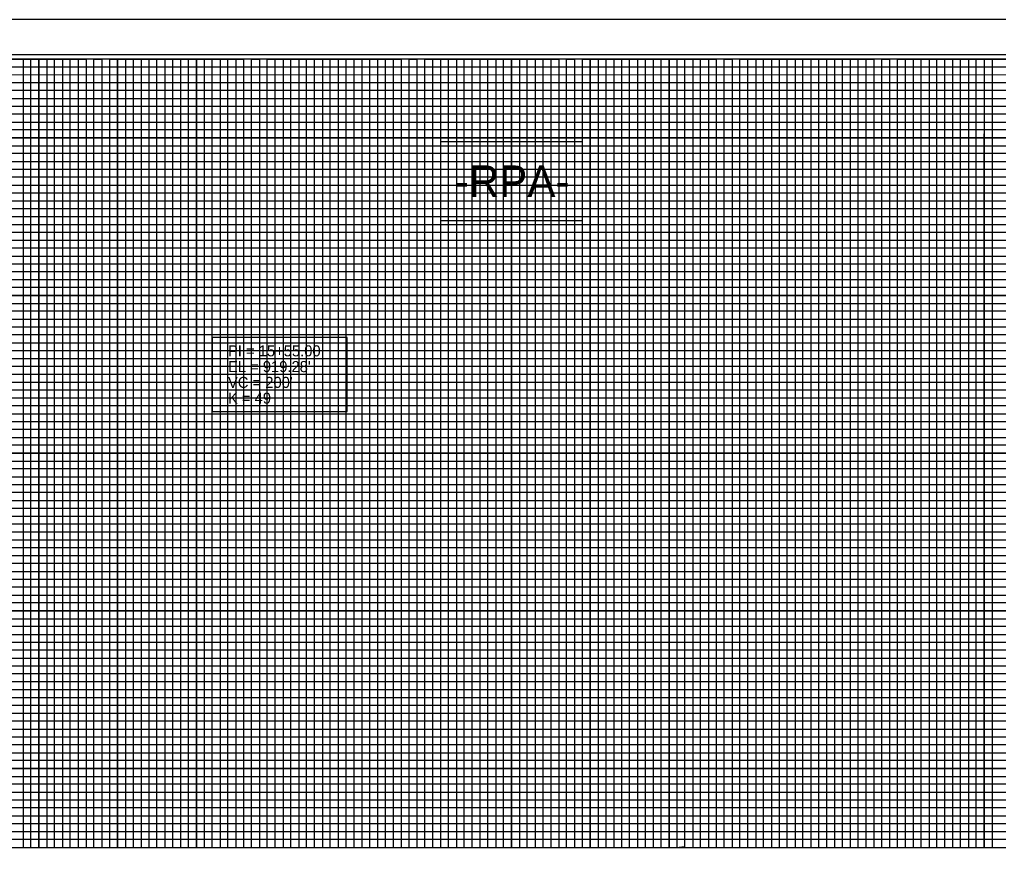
# Model space of a CAD drawing. Extents: x 1648862 to 1650715, y 820691 to 821791.
# Drawn here: x 1649467 to 1650088, y 821252 to 821791 of the extents above; entities that cross this region are included whole.
import ezdxf

# ---------------------------------------------------------------- set-up
doc = ezdxf.new("R2010")
doc.units = 0
for name, color, linetype in [('Exist Vertical Profile Horizontal Axis Label Major', 7, 'Continuous'), ('Prop Grid Mask', 7, 'Continuous'), ('Prop Vertical Profile Curve Label', 7, 'Continuous'), ('Prop VPI Label', 7, 'Continuous'), ('Sheet Cutting Line CELL', 7, 'Continuous'), ('Sheet DOT Grid CELL', 7, 'Continuous'), ('Sheet Layout Profile Border Port 1', 7, 'Continuous'), ('Sheet Plot Border Inside CELL', 7, 'Continuous'), ('Sheet Plot Border Outside CELL', 7, 'Continuous'), ('Sheet Profile CELL', 7, 'Continuous'), ('Sheet Profile Grid Major CELL', 7, 'Continuous'), ('Sheet Profile Grid Middle CELL', 7, 'Continuous'), ('Sheet Profile Grid Minor CELL', 7, 'Continuous')]:
    doc.layers.add(name, color=color, linetype=linetype)

msp = doc.modelspace()

# ---------------------------------------------------------------- linework, layer by layer
at = {"layer": 'Prop Grid Mask'}
for points in [[(1649734.28, 821713.52), (1649734.28, 821663.52), (1649824.28, 821663.52), (1649824.28, 821713.52)], [(1649589.28, 821589.43), (1649589.28, 821542.43), (1649674.97, 821542.43), (1649674.97, 821589.43)]]:
    msp.add_lwpolyline(points, close=True, dxfattribs=at)
at = {"layer": 'Sheet Cutting Line CELL'}
msp.add_line((1650546.28, 821791.02), (1648862.28, 821791.02), dxfattribs=at)
at = {"layer": 'Sheet DOT Grid CELL'}
for p, q in [((1649479.28, 821266.02), (1649479.28, 821766.02)), ((1649529.28, 821266.02), (1649529.28, 821766.02)), ((1649579.28, 821266.02), (1649579.28, 821766.02)), ((1649629.28, 821266.02), (1649629.28, 821766.02)), ((1649679.28, 821266.02), (1649679.28, 821766.02)), ((1649729.28, 821266.02), (1649729.28, 821766.02)), ((1649779.28, 821266.02), (1649779.28, 821766.02)), ((1649829.28, 821266.02), (1649829.28, 821766.02)), ((1649879.28, 821266.02), (1649879.28, 821766.02)), ((1649929.28, 821266.02), (1649929.28, 821766.02)), ((1649979.28, 821266.02), (1649979.28, 821766.02)), ((1650029.28, 821266.02), (1650029.28, 821766.02)), ((1650079.28, 821266.02), (1650079.28, 821718.48)), ((1650329.23, 821716.02), (1649029.28, 821716.02)), ((1650329.23, 821666.02), (1649029.28, 821666.02)), ((1650329.28, 821616.02), (1649029.28, 821616.02)), ((1650529.28, 821566.02), (1649029.28, 821566.02)), ((1650529.28, 821516.02), (1649029.28, 821516.02)), ((1650529.28, 821466.02), (1649029.28, 821466.02)), ((1650529.28, 821416.02), (1649029.28, 821416.02)), ((1650529.28, 821366.02), (1649029.28, 821366.02)), ((1650529.28, 821316.02), (1649029.28, 821316.02))]:
    msp.add_line(p, q, dxfattribs=at)
at = {"layer": 'Sheet Layout Profile Border Port 1'}
msp.add_lwpolyline([(1649079.28, 821604.97), (1649079.28, 821266.02), (1650479.28, 821266.02), (1650479.28, 821604.97)], dxfattribs=at)
at = {"layer": 'Sheet Plot Border Inside CELL'}
msp.add_lwpolyline([(1648875.28, 820713.47), (1650541.78, 820713.47), (1650541.78, 821768.57), (1648875.28, 821768.57)], close=True, dxfattribs=at)
at = {"layer": 'Sheet Plot Border Outside CELL'}
msp.add_lwpolyline([(1648862.28, 820691.02), (1650546.28, 820691.02), (1650546.28, 821791.02), (1648862.28, 821791.02)], close=True, dxfattribs=at)
at = {"layer": 'Sheet Profile CELL'}
msp.add_line((1649029.28, 821266.02), (1650529.28, 821266.02), dxfattribs=at)
msp.add_lwpolyline([(1650529.28, 821766.02), (1649029.28, 821766.02), (1649029.28, 820716.02), (1650529.28, 820716.02)], close=True, dxfattribs=at)
at = {"layer": 'Sheet Profile Grid Major CELL'}
for points in [[(1649429.23, 821766.02), (1649479.23, 821766.02), (1649479.23, 821266.02), (1649529.23, 821266.02), (1649529.23, 821766.02), (1649579.23, 821766.02), (1649579.23, 821266.02), (1649629.23, 821266.02), (1649629.23, 821766.02), (1649679.23, 821766.02), (1649679.23, 821266.02), (1649729.23, 821266.02), (1649729.23, 821766.02), (1649779.23, 821766.02), (1649779.23, 821266.02), (1649829.23, 821266.02), (1649829.23, 821766.02), (1649879.23, 821766.02), (1649879.23, 821266.02), (1649929.23, 821266.02), (1649929.23, 821766.02), (1649979.23, 821766.02), (1649979.23, 821266.02), (1650029.23, 821266.02), (1650029.23, 821766.02), (1650079.23, 821766.02), (1650079.23, 821266.02), (1650129.23, 821266.02)], [(1649029.23, 821716.02), (1650329.23, 821716.02)], [(1650329.23, 821666.02), (1649029.23, 821666.02), (1649029.23, 821616.02), (1650329.23, 821616.02)], [(1650529.23, 821566.02), (1649029.23, 821566.02), (1649029.23, 821516.02), (1650529.23, 821516.02)], [(1650529.23, 821466.02), (1649029.23, 821466.02), (1649029.23, 821416.02), (1650529.23, 821416.02)], [(1650529.23, 821366.02), (1649029.23, 821366.02), (1649029.23, 821366.02), (1649029.23, 821316.02), (1650529.23, 821316.02)]]:
    msp.add_lwpolyline(points, dxfattribs=at)
at = {"layer": 'Sheet Profile Grid Middle CELL'}
msp.add_line((1649029.23, 821741.02), (1650179.23, 821741.02), dxfattribs=at)
for points in [[(1649454.23, 821766.02), (1649504.23, 821766.02), (1649504.23, 821266.02), (1649554.23, 821266.02), (1649554.23, 821766.02), (1649604.23, 821766.02), (1649604.23, 821266.02), (1649654.23, 821266.02), (1649654.23, 821266.02), (1649654.23, 821766.02), (1649704.23, 821766.02), (1649704.23, 821266.02), (1649754.23, 821266.02), (1649754.23, 821766.02), (1649804.23, 821766.02), (1649804.23, 821266.02), (1649854.23, 821266.02), (1649854.23, 821766.02), (1649904.23, 821766.02), (1649904.23, 821266.02), (1649954.23, 821266.02), (1649954.23, 821766.02), (1650004.23, 821766.02), (1650004.23, 821266.02), (1650054.23, 821266.02), (1650054.23, 821766.02), (1650104.23, 821766.02)], [(1650329.23, 821691.02), (1649029.23, 821691.02), (1649029.23, 821641.02), (1650329.23, 821641.02)], [(1650529.23, 821591.02), (1649029.23, 821591.02), (1649029.23, 821541.02), (1650354.23, 821541.02)], [(1650529.23, 821491.02), (1649029.23, 821491.02), (1649029.23, 821441.02), (1650529.23, 821441.02)], [(1650529.23, 821391.02), (1649029.23, 821391.02), (1649029.23, 821341.02), (1650529.23, 821341.02)], [(1650529.23, 821291.02), (1649029.23, 821291.02)]]:
    msp.add_lwpolyline(points, dxfattribs=at)
at = {"layer": 'Sheet Profile Grid Minor CELL'}
for p, q in [((1649079.23, 821761.02), (1650179.23, 821761.02)), ((1650179.23, 821755.98), (1649079.23, 821755.67)), ((1649079.28, 821761.02), (1650037.42, 821761.02)), ((1649079.23, 821751.02), (1650179.23, 821751.02)), ((1650329.18, 821631.02), (1649079.23, 821631.02)), ((1650329.23, 821626.02), (1649079.23, 821626.02)), ((1650329.23, 821621.02), (1649079.23, 821621.02)), ((1649079.23, 821611.02), (1650329.23, 821611.02)), ((1650329.23, 821606.02), (1649079.23, 821606.02)), ((1649079.23, 821601.02), (1650479.23, 821601.02)), ((1650479.23, 821581.02), (1649079.23, 821581.02)), ((1649079.23, 821576.02), (1650479.23, 821576.02)), ((1650479.23, 821556.02), (1649079.23, 821556.02)), ((1649079.23, 821551.02), (1650479.23, 821551.02)), ((1650479.23, 821531.02), (1649079.23, 821531.02)), ((1649079.23, 821526.02), (1650479.23, 821526.02)), ((1650479.23, 821521.02), (1649079.23, 821521.02)), ((1649079.23, 821511.02), (1650479.23, 821511.02)), ((1650479.23, 821506.02), (1649079.23, 821506.02)), ((1649079.23, 821501.02), (1650479.23, 821501.02)), ((1650479.23, 821496.02), (1649079.23, 821496.02)), ((1649079.23, 821486.02), (1650479.23, 821486.02)), ((1650479.23, 821481.02), (1649079.23, 821481.02)), ((1649079.23, 821476.02), (1650479.23, 821476.02)), ((1650479.23, 821471.02), (1649079.23, 821471.02)), ((1649079.23, 821461.02), (1650479.23, 821461.02)), ((1650479.23, 821456.02), (1649079.23, 821456.02)), ((1649079.23, 821451.02), (1650479.23, 821451.02)), ((1650479.23, 821446.02), (1649079.23, 821446.02)), ((1649079.23, 821436.02), (1650479.23, 821436.02)), ((1650479.23, 821431.02), (1649079.23, 821431.02)), ((1649079.23, 821426.02), (1650479.23, 821426.02)), ((1650479.23, 821421.02), (1649079.23, 821421.02)), ((1649079.23, 821411.02), (1650479.23, 821411.02)), ((1650479.23, 821406.02), (1649079.23, 821406.02)), ((1649079.23, 821401.02), (1650479.23, 821401.02)), ((1650479.23, 821396.02), (1649079.23, 821396.02)), ((1649079.23, 821386.02), (1650479.23, 821386.02)), ((1650479.23, 821381.02), (1649079.23, 821381.02)), ((1650479.23, 821376.02), (1649079.23, 821376.02)), ((1650479.23, 821371.02), (1649079.23, 821371.02)), ((1649079.23, 821361.02), (1650479.23, 821361.02)), ((1650479.23, 821356.02), (1649079.23, 821356.02)), ((1649079.23, 821351.02), (1650479.23, 821351.02)), ((1650479.23, 821346.02), (1649079.23, 821346.02)), ((1649079.23, 821336.02), (1650479.23, 821336.02)), ((1650479.23, 821331.02), (1649079.23, 821331.02)), ((1649079.23, 821326.02), (1650479.23, 821326.02)), ((1650479.23, 821321.02), (1649079.23, 821321.02)), ((1649079.23, 821311.02), (1650479.23, 821311.02)), ((1650479.23, 821306.02), (1649079.23, 821306.02)), ((1649079.23, 821301.02), (1650479.23, 821301.02)), ((1650479.23, 821296.02), (1649079.23, 821296.02)), ((1649079.23, 821286.02), (1650479.23, 821286.02)), ((1650479.23, 821281.02), (1649079.23, 821281.02)), ((1649079.23, 821276.02), (1650479.23, 821276.02))]:
    msp.add_line(p, q, dxfattribs=at)
for points in [[(1649464.23, 821766.02), (1649469.23, 821766.02), (1649469.23, 821266.02), (1649474.23, 821266.02), (1649474.23, 821766.02), (1649484.23, 821766.02), (1649484.23, 821266.02), (1649489.23, 821266.02), (1649489.23, 821766.02), (1649494.23, 821766.02), (1649494.23, 821266.02), (1649499.23, 821266.02), (1649499.23, 821766.02), (1649509.23, 821766.02), (1649509.23, 821266.02), (1649514.23, 821266.02), (1649514.23, 821766.02), (1649519.23, 821766.02), (1649519.23, 821266.02), (1649524.23, 821266.02), (1649524.23, 821766.02), (1649534.23, 821766.02), (1649534.23, 821266.02), (1649539.23, 821266.02), (1649539.23, 821766.02), (1649544.23, 821766.02), (1649544.23, 821266.02), (1649549.23, 821266.02), (1649549.23, 821766.02), (1649559.23, 821766.02), (1649559.23, 821266.02), (1649564.23, 821266.02), (1649564.23, 821766.02), (1649569.23, 821766.02), (1649569.23, 821266.02), (1649574.23, 821266.02), (1649574.23, 821766.02), (1649584.23, 821766.02), (1649584.23, 821266.02), (1649589.23, 821266.02), (1649589.23, 821766.02), (1649594.23, 821766.02), (1649594.23, 821266.02), (1649599.23, 821266.02), (1649599.23, 821766.02), (1649609.23, 821766.02)], [(1649609.23, 821766.02), (1649609.23, 821266.02), (1649614.23, 821266.02), (1649614.23, 821766.02), (1649619.23, 821766.02), (1649619.23, 821266.02), (1649624.23, 821266.02), (1649624.23, 821766.02), (1649634.23, 821766.02), (1649634.23, 821266.02), (1649639.23, 821266.02), (1649639.23, 821766.02), (1649644.23, 821766.02), (1649644.23, 821266.02), (1649649.23, 821266.02), (1649649.23, 821766.02), (1649659.23, 821766.02), (1649659.23, 821266.02), (1649664.23, 821266.02), (1649664.23, 821766.02), (1649669.23, 821766.02), (1649669.23, 821266.02), (1649674.23, 821266.02), (1649674.23, 821766.02), (1649684.23, 821766.02), (1649684.23, 821266.02), (1649689.23, 821266.02), (1649689.23, 821766.02), (1649694.23, 821766.02), (1649694.23, 821266.02), (1649699.23, 821266.02), (1649699.23, 821766.02), (1649709.23, 821766.02), (1649709.23, 821266.02), (1649714.23, 821266.02), (1649714.23, 821766.02), (1649719.23, 821766.02), (1649719.23, 821266.02), (1649724.23, 821266.02), (1649724.23, 821766.02), (1649734.23, 821766.02), (1649734.23, 821266.02), (1649734.23, 821266.02), (1649739.23, 821266.02), (1649739.23, 821766.02), (1649744.23, 821766.02), (1649744.23, 821266.02), (1649749.23, 821266.02), (1649749.23, 821766.02), (1649759.23, 821766.02), (1649759.23, 821266.02), (1649764.23, 821266.02), (1649764.23, 821766.02), (1649769.23, 821766.02), (1649769.23, 821266.02), (1649774.23, 821266.02), (1649774.23, 821766.02), (1649784.23, 821766.02), (1649784.23, 821266.02), (1649789.23, 821266.02), (1649789.23, 821766.02), (1649794.23, 821766.02), (1649794.23, 821266.02), (1649799.23, 821266.02), (1649799.23, 821766.02), (1649809.23, 821766.02), (1649809.23, 821266.02), (1649814.23, 821266.02), (1649814.23, 821766.02), (1649819.23, 821766.02), (1649819.23, 821266.02), (1649824.23, 821266.02), (1649824.23, 821766.02), (1649834.23, 821766.02), (1649834.23, 821266.02), (1649839.23, 821266.02), (1649839.23, 821766.02), (1649844.23, 821766.02), (1649844.23, 821266.02), (1649849.23, 821266.02), (1649849.23, 821766.02), (1649859.23, 821766.02), (1649859.23, 821266.02), (1649864.23, 821266.02), (1649864.23, 821766.02), (1649869.23, 821766.02), (1649869.23, 821266.02), (1649874.23, 821266.02), (1649874.23, 821766.02), (1649884.23, 821766.02), (1649884.23, 821266.02), (1649888.93, 821266.57), (1649889.23, 821266.02), (1649889.23, 821766.02), (1649894.23, 821766.02), (1649894.23, 821266.02), (1649899.23, 821266.02), (1649899.23, 821766.02), (1649909.23, 821766.02), (1649909.23, 821266.02), (1649914.23, 821266.02)], [(1649914.23, 821266.02), (1649914.23, 821766.02), (1649919.23, 821766.02), (1649919.23, 821266.02), (1649924.23, 821266.02), (1649924.23, 821766.02), (1649934.23, 821766.02), (1649934.23, 821266.02), (1649939.23, 821266.02), (1649939.23, 821766.02), (1649944.23, 821766.02), (1649944.23, 821266.02), (1649949.23, 821266.02), (1649949.23, 821766.02), (1649959.23, 821766.02), (1649959.23, 821266.02), (1649964.23, 821266.02), (1649964.23, 821766.02), (1649969.23, 821766.02), (1649969.23, 821266.02), (1649974.23, 821266.02), (1649974.23, 821766.02), (1649984.23, 821766.02), (1649984.23, 821266.02), (1649989.23, 821266.02), (1649989.23, 821766.02), (1649994.23, 821766.02), (1649994.23, 821266.02), (1649999.23, 821266.02), (1649999.23, 821766.02), (1650009.23, 821766.02), (1650009.23, 821266.02), (1650014.23, 821266.02), (1650014.23, 821766.02), (1650019.23, 821766.02), (1650019.23, 821266.02), (1650024.23, 821266.02), (1650024.23, 821766.02), (1650034.23, 821766.02), (1650034.23, 821266.02), (1650039.23, 821266.02), (1650039.23, 821766.02), (1650044.23, 821766.02), (1650044.23, 821266.02), (1650049.23, 821266.02), (1650049.23, 821766.02), (1650059.23, 821766.02), (1650059.23, 821266.02), (1650064.23, 821266.02), (1650064.23, 821766.02), (1650069.23, 821766.02), (1650069.23, 821266.02), (1650074.23, 821266.02), (1650074.23, 821766.02), (1650084.23, 821766.02), (1650084.23, 821266.02), (1650089.23, 821266.02)], [(1650179.23, 821746.02), (1649079.23, 821746.02), (1649079.23, 821736.02), (1650329.23, 821736.02)], [(1650329.18, 821731.02), (1649079.23, 821731.02), (1649079.23, 821726.02), (1650329.23, 821726.02)], [(1650329.23, 821721.02), (1649079.23, 821721.02), (1649079.23, 821711.02), (1650329.23, 821711.02)], [(1650329.23, 821706.02), (1649079.23, 821706.02), (1649079.23, 821701.02), (1650329.23, 821701.02)], [(1650329.23, 821696.02), (1649079.23, 821696.02), (1649079.23, 821686.02), (1650329.23, 821686.02)], [(1650329.23, 821681.02), (1649079.23, 821681.02), (1649079.23, 821676.02), (1650329.23, 821676.02)], [(1650329.23, 821671.02), (1649079.23, 821671.02), (1649079.23, 821661.02), (1650329.23, 821661.02)], [(1650329.23, 821655.92), (1649079.33, 821655.92), (1649079.33, 821651.02), (1650329.23, 821651.02)], [(1650329.23, 821646.02), (1649079.23, 821646.02), (1649079.23, 821636.02), (1650329.23, 821636.02)], [(1650479.23, 821596.02), (1649079.23, 821596.02), (1649079.23, 821586.02), (1650479.23, 821586.02)], [(1650479.23, 821571.02), (1649079.23, 821571.02), (1649079.23, 821561.02), (1650479.23, 821561.02)], [(1650479.23, 821546.02), (1649079.23, 821546.02), (1649079.23, 821536.02), (1650479.23, 821536.02)], [(1650479.23, 821271.02), (1649079.23, 821271.02)]]:
    msp.add_lwpolyline(points, dxfattribs=at)

# ---------------------------------------------------------------- texts
at = {"layer": 'Exist Vertical Profile Horizontal Axis Label Major'}
msp.add_text('-RPA-', height=20, dxfattribs=at).set_placement((1649743.22, 821678.52))
at = {"layer": 'Prop Vertical Profile Curve Label'}
for s, p in [("VC = 200'", (1649599.28, 821557.43)), ('K = 49', (1649599.28, 821547.43))]:
    msp.add_text(s, height=7, dxfattribs=at).set_placement(p)
at = {"layer": 'Prop VPI Label'}
for s, p in [('PI = 15+55.00', (1649599.28, 821577.43)), ("EL = 919.28'", (1649599.28, 821567.43))]:
    msp.add_text(s, height=7, dxfattribs=at).set_placement(p)

doc.saveas('drawing.dxf')
